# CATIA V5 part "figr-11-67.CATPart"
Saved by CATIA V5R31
Part number: Part2
Bounding box of the stored display mesh (mm): x -69 to 69, y -70.588 to 84.546, z -60.219 to 83.037
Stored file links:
  D:\PROJECTS\Project 2021\US EDITION\CATIA V5 6R 2021\Resources\Part Files\c11_catia_v5_6r2021_prt\figr-11-67.CATPart
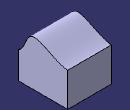
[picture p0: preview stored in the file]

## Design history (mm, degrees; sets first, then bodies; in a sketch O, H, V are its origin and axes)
Set1
  Extrude1: Element1 Sketch2, Lim1 134, Lim2 101, Direction yz-plane
Body1 (main body)
  Sketch1 on yz-plane, origin (0, 0, 0), H (0, 1, 0), V (0, 0, 1)
    line L1 (-70.5879, 56.2311) -> (84.546, 56.2311)
    line L2 (84.546, 56.2311) -> (84.546, -60.2191)
    line L3 (84.546, -60.2191) -> (-70.5879, -60.2191)
    line L4 (-70.5879, -60.2191) -> (-70.5879, 56.2311)
    horizontal: L1 H, L3 H
    vertical: L2 V, L4 V
  Pad1: profile Sketch1, direction (1, 0, 0), length 69, mirrored extent
  SewSurface1: SewingRemoveFace face of Pad1, SplitPlane Extrude1
  Sketch2 on yz-plane, origin (0, 0, 0), H (0, 1, 0), V (0, 0, 1)
    spline S1 through (-101.2957, 16.3509) (-51.8443, 49.0526) (-38.418, 74.5863) (34.1283, 62.9515) (100.0993, 49.0526)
